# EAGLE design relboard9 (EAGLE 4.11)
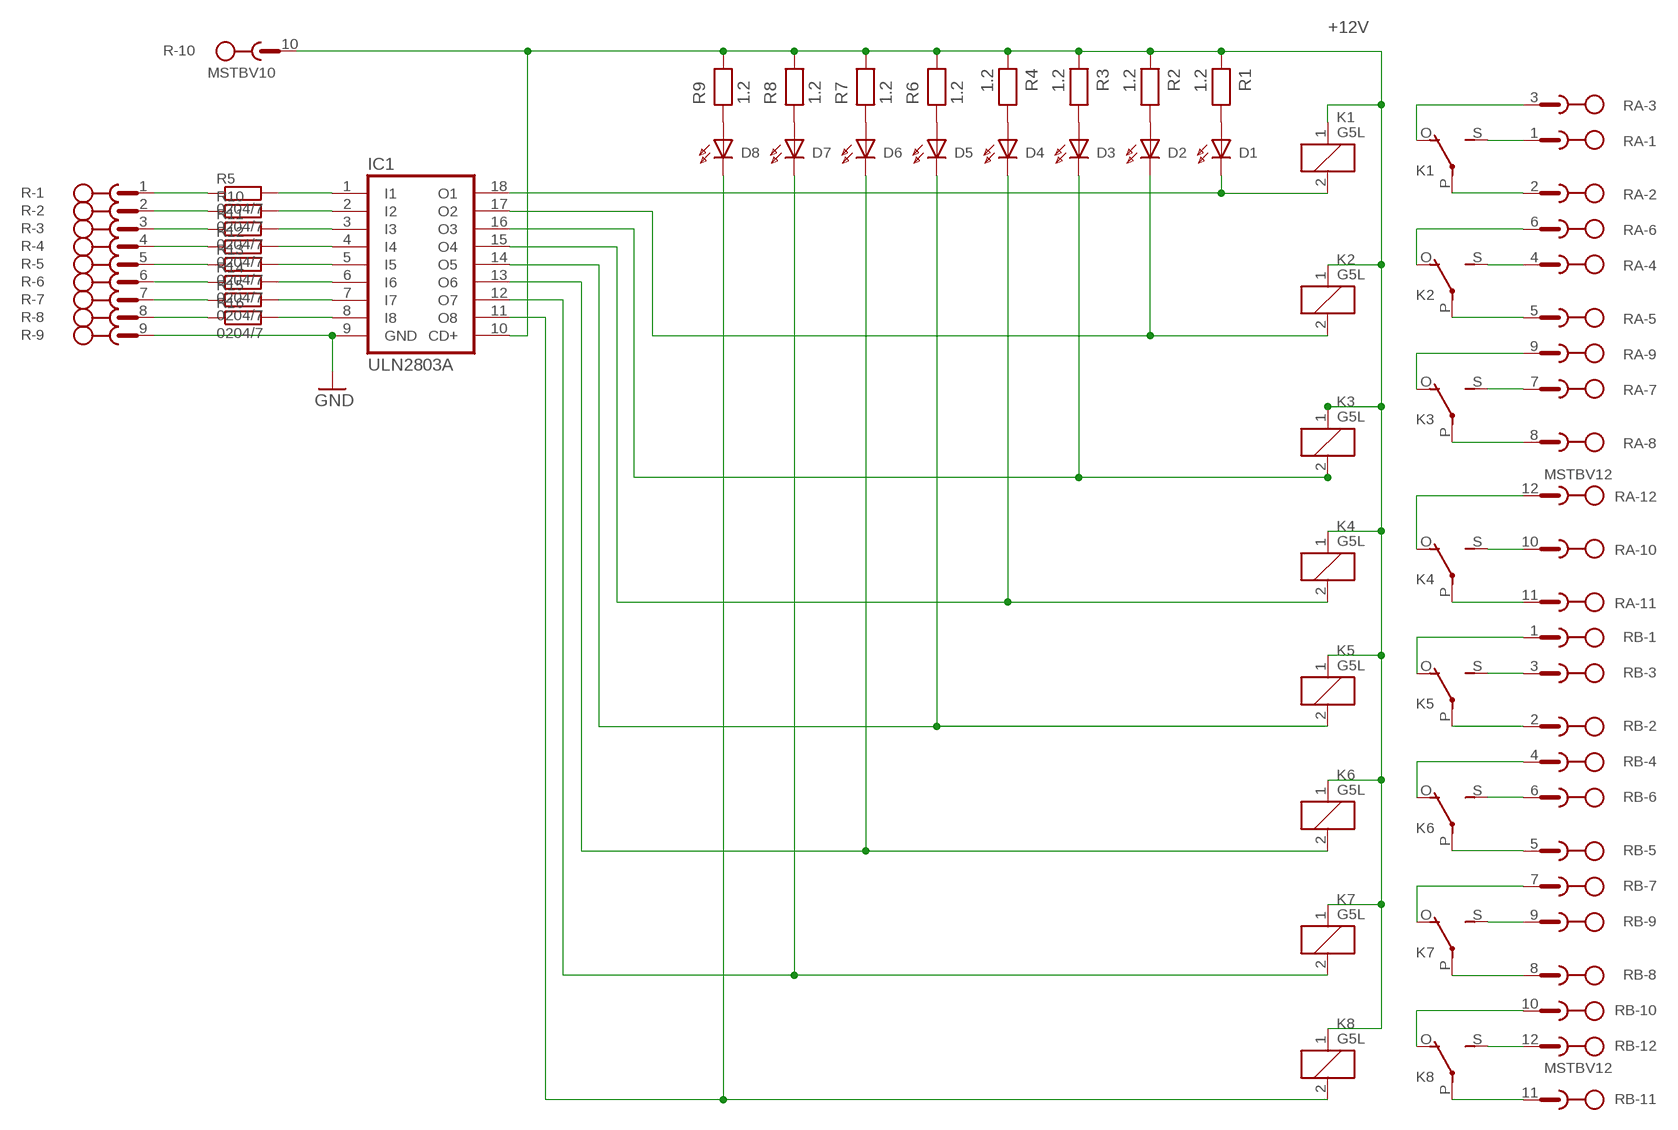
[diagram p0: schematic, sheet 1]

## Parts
D1  LED3  [LED3]
D2  LED3  [LED3]
D3  LED3  [LED3]
D4  LED3  [LED3]
D5  LED3  [LED3]
D6  LED3  [LED3]
D7  LED3  [LED3]
D8  LED3  [LED3]
IC1  ULN2803A  [DIL18]
K1  G5L  [G5L]
K2  G5L  [G5L]
K3  G5L  [G5L]
K4  G5L  [G5L]
K5  G5L  [G5L]
K6  G5L  [G5L]
K7  G5L  [G5L]
K8  G5L  [G5L]
R  MSTBV10  [MSTBV10]
R1  1.2  RESEU-10  [R-10]
R2  1.2  RESEU-10  [R-10]
R3  1.2  RESEU-10  [R-10]
R4  1.2  RESEU-10  [R-10]
R5  0204/7  [0204/7]
R6  1.2  RESEU-10  [R-10]
R7  1.2  RESEU-10  [R-10]
R8  1.2  RESEU-10  [R-10]
R9  1.2  RESEU-10  [R-10]
R10  0204/7  [0204/7]
R11  0204/7  [0204/7]
R12  0204/7  [0204/7]
R13  0204/7  [0204/7]
R14  0204/7  [0204/7]
R15  0204/7  [0204/7]
R16  0204/7  [0204/7]
RA  MSTBV12  [MSTBV12]
RB  MSTBV12  [MSTBV12]

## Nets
+12V: IC1.10(CD+) K1.1 K2.1 K3.1 K4.1 K5.1 K6.1 K7.1 K8.1 R1.1 R2.1 R3.1 R4.1 R6.2 R7.2 R8.2 R9.2 R.10
GND: IC1.9(GND) R.9
N$1: D3.K IC1.16(O3) K3.2
N$2: D2.K IC1.17(O2) K2.2
N$3: K4.P(S:P) RA.11
N$4: K2.S(S:S) RA.4
N$5: K4.S(S:S) RA.10
N$6: K2.P(S:P) RA.5
N$7: IC1.5(I5) R13.2
N$8: K3.O(S:O) RA.9
N$9: K1.P(S:P) RA.2
N$10: K1.S(S:S) RA.1
N$11: K3.P(S:P) RA.8
N$12: K4.O(S:O) RA.12
N$13: K3.S(S:S) RA.7
N$14: IC1.6(I6) R14.2
N$15: K2.O(S:O) RA.6
N$16: K1.O(S:O) RA.3
N$17: K5.S(S:S) RB.3
N$18: IC1.7(I7) R15.2
N$19: D4.K IC1.15(O4) K4.2
N$20: IC1.8(I8) R16.2
N$21: IC1.2(I2) R10.2
N$22: IC1.3(I3) R11.2
N$23: IC1.4(I4) R12.2
N$24: IC1.1(I1) R5.2
N$25: D1.A R1.2
N$26: D2.A R2.2
N$27: D3.A R3.2
N$28: D4.A R4.2
N$29: D8.K IC1.11(O8) K8.2
N$30: D7.K IC1.12(O7) K7.2
N$31: D6.K IC1.13(O6) K6.2
N$32: D5.K IC1.14(O5) K5.2
N$33: D1.K IC1.18(O1) K1.2
N$35: D5.A R6.1
N$36: D6.A R7.1
N$37: R5.1 R.1
N$38: R10.1 R.2
N$39: D7.A R8.1
N$40: D8.A R9.1
N$41: K5.O(S:O) RB.1
N$42: K5.P(S:P) RB.2
N$43: R11.1 R.3
N$44: K7.O(S:O) RB.7
N$45: K6.S(S:S) RB.6
N$46: K8.S(S:S) RB.12
N$47: K6.P(S:P) RB.5
N$48: K6.O(S:O) RB.4
N$49: K8.P(S:P) RB.11
N$50: K7.P(S:P) RB.8
N$51: K8.O(S:O) RB.10
N$52: R12.1 R.4
N$53: R13.1 R.5
N$54: R14.1 R.6
N$55: K7.S(S:S) RB.9
N$56: R15.1 R.7
N$57: R16.1 R.8

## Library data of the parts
D1-D8 = led:LED3
IC1 = uln:ULN2803A
K1-K8 = relais:G5L
R = pho508e:MSTBV10
R1-R4 R6-R9 = discrete:RESEU-10
R5 R10-R16 = r:0204/7
RA RB = pho508e:MSTBV12

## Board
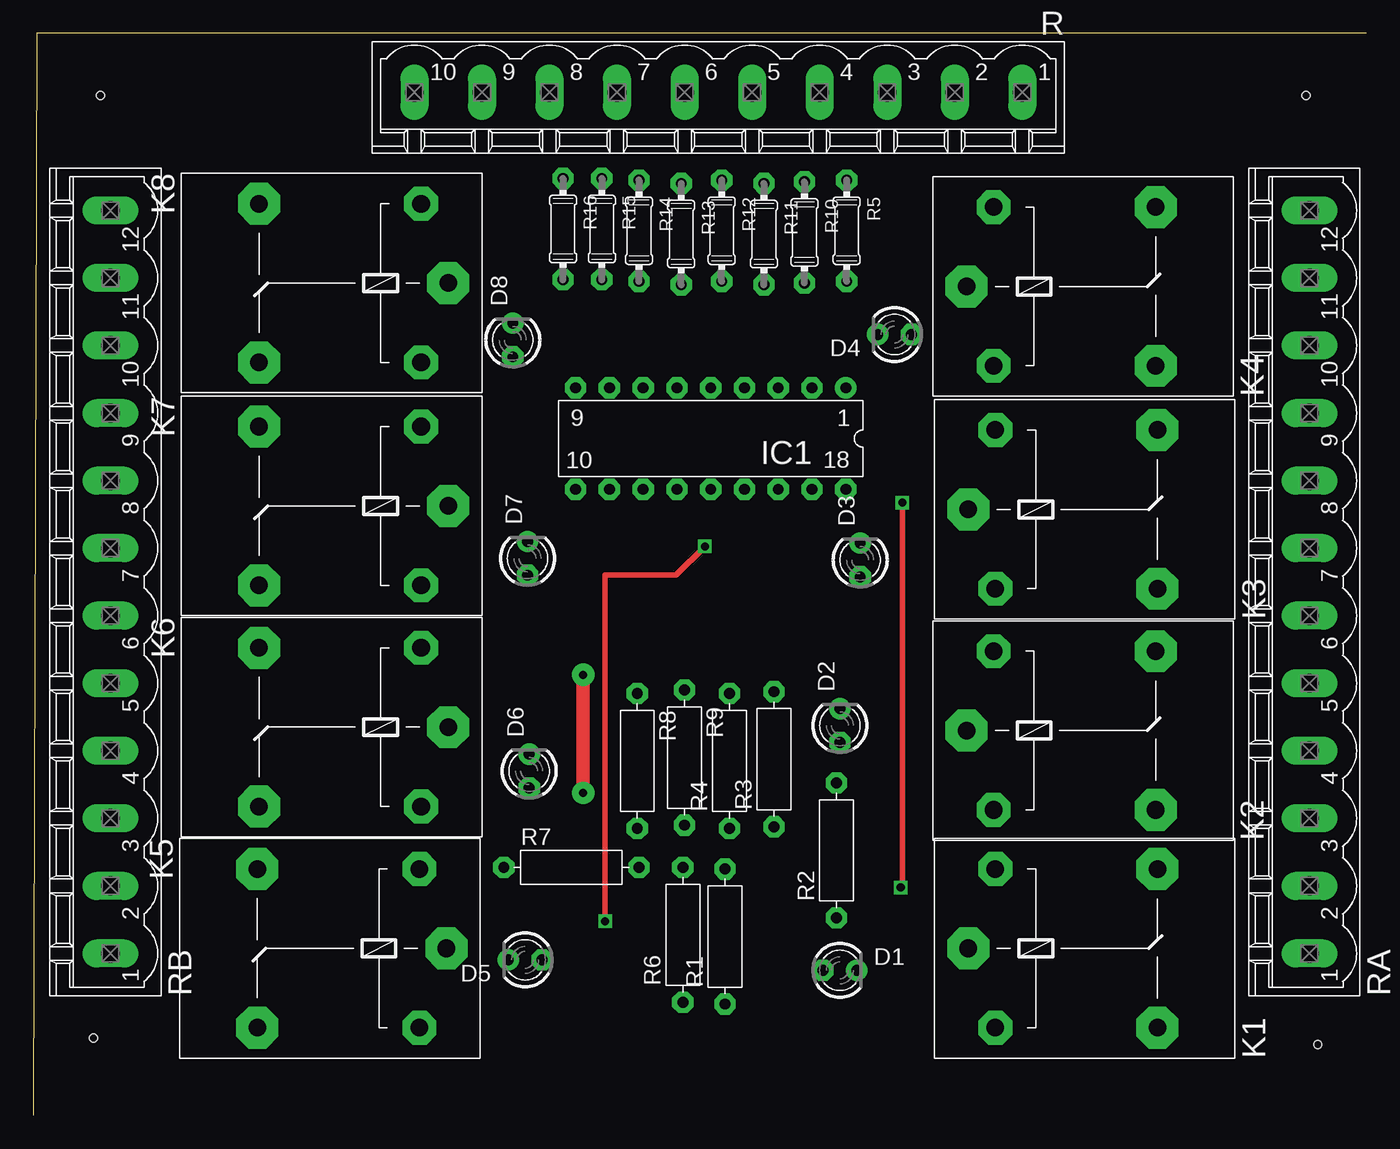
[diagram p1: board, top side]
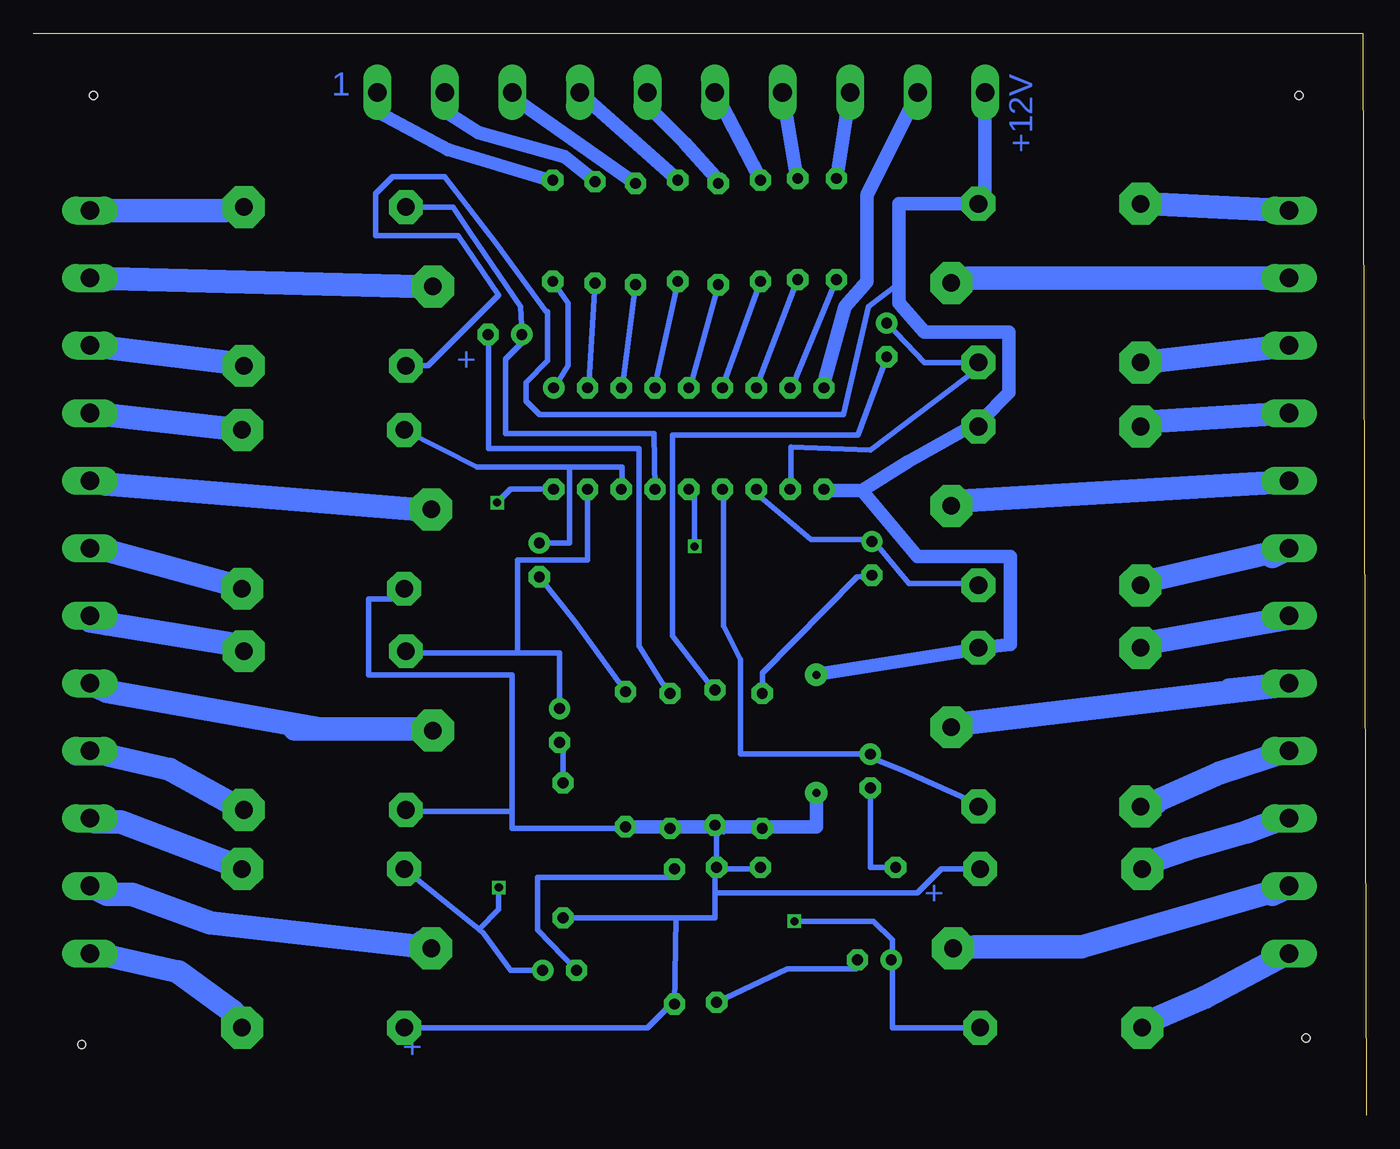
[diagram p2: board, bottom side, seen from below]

Size 100.25 x 81.4 mm. Coordinates in mm from the lower left corner, seen from the top.
Outline: 100.25,81.4 0.25,81.4 0,0
Copper layers (1*16): Top 0.035mm / dielectric 1.5mm / Bottom 0.035mm
Design rules "default": minimum track width 10mil, minimum drill 24mil, track to track 8mil, track to pad 8mil, pad to pad 8mil, via to via 8mil, smd to smd 8mil, copper to edge 40mil, drill to drill 8mil, minimum pad ring 10mil, minimum via ring 8mil, stop-mask expansion 0mil, vias tented up to drill 0mil, thermal gap 10mil
Holes 0.61 mm at 5.04,76.7 95.72,76.7 96.61,5.33 4.53,5.84

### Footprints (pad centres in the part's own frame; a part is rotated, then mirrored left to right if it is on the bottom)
LED3 = drill 0.813 pad 1.6 octagon: A -1.27,0 | drill 0.813 pad 1.6 round: K 1.27,0
DIL18 = drill 0.813 pad 1.6 round: 1 -10.16,-3.81 | drill 0.813 pad 1.6 octagon: 2 -7.62,-3.81; 3 -5.08,-3.81; 4 -2.54,-3.81; 5 0,-3.81; 6 2.54,-3.81; 7 5.08,-3.81; 8 7.62,-3.81; 9 10.16,-3.81; 10 10.16,3.81; 11 7.62,3.81; 12 5.08,3.81; 13 2.54,3.81; 14 0,3.81; 15 -2.54,3.81; 16 -5.08,3.81; 17 -7.62,3.81; 18 -10.16,3.81
G5L = drill 1.321 pad 2.54 octagon: 1 2.032,-5.969; 2 2.032,5.969 | drill 1.321 pad 3.15 octagon: O 14.224,5.969; P 0,0; S 14.224,-5.969
MSTBV10 = drill 1.397 pad 1.905 long: 1 -22.86,0; 2 -17.78,0; 3 -12.7,0; 4 -7.62,0; 5 -2.54,0; 6 2.54,0; 7 7.62,0; 8 12.7,0; 9 17.78,0; 10 22.86,0
R-10 = drill 0.813 pad 1.6 octagon: 1 -5.08,0; 2 5.08,0
0204/7 = drill 0.813 pad 1.6 octagon: 1 -3.81,0; 2 3.81,0
MSTBV12 = drill 1.397 pad 1.905 long: 1 -27.94,0; 2 -22.86,0; 3 -17.78,0; 4 -12.7,0; 5 -7.62,0; 6 -2.54,0; 7 2.54,0; 8 7.62,0; 9 12.7,0; 10 17.78,0; 11 22.86,0; 12 27.94,0

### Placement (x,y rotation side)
D1  60.67,10.92 0 top
D2  60.67,29.33 90 top
D3  62.19,41.78 90 top
D4  64.77,58.74 180 top
D5  36.99,11.7 180 top
D6  37.3,25.9 90 top
D7  37.17,41.91 90 top
D8  36.07,58.33 90 top
IC1  50.95,50.91 180 top
K1  70.32,12.57 0 top
K2  70.19,28.95 0 top
K3  70.32,45.59 0 top
K4  70.19,62.35 0 top
K5  31.08,12.57 180 top
K6  31.2,29.21 180 top
K7  31.2,45.84 180 top
K8  31.2,62.61 180 top
R  51.52,76.96 180 top
R1  52.03,13.46 90 top
R2  60.41,19.93 90 top
R3  55.71,26.79 90 top
R4  52.37,26.67 90 top
R5  61.18,66.54 270 top
R6  48.86,13.58 90 top
R7  40.47,18.66 0 top
R8  45.43,26.67 270 top
R9  48.98,26.92 270 top
R10  58,66.42 270 top
R11  54.95,66.29 270 top
R12  51.78,66.54 270 top
R13  48.73,66.29 270 top
R14  45.55,66.54 270 top
R15  42.76,66.67 270 top
R16  39.84,66.67 270 top
RA  95.97,40.13 90 top
RB  5.8,40.13 90 top

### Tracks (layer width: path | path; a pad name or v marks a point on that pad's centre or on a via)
+12V  (via drill 0.61 pad 1.68)
  Top 1.016: v41.36,24.25 v41.36,33.14
  Bottom 0.406: 45.81,21.71 R8.2 45.17,21.71 | R9.2 48.35,21.71 48.48,21.59 48.86,21.97 48.98,21.97 48.35,21.33 48.86,21.59 | 52.16,21.71 R4.1 52.79,21.71 | 28.66,69.34 K8.1 29.3,68.07 | 29.3,51.81 K7.1 | 40.73,46.98 IC1.10 | K7.1 29.43,51.94 | 28.6,76.39 28.54,76.32 | 28.6,76.39 28.66,76.45 R.10 28.66,76.32 28.6,76.39 | 28.92,51.94 28.92,52.32 | K7.1 28.66,51.56 | K6.1 31.33,34.67 28.99,35.13 | R6.2 48.86,21.59 | K1.1 54.06,6.6 52.29,8.38 R1.1 51.9,14.85 | R7.2 45.81,18.54 48.35,18.54 R6.2 | 51.9,14.85 48.98,14.85 48.98,16.76 | 48.98,16.76 48.98,17.9 R6.2 | 48.98,16.76 33.74,16.76 31.97,18.54 K5.1 | 64.22,22.86 71.84,22.86 K2.1 | 64.22,22.86 64.22,21.59 48.86,21.59 | 64.22,22.86 64.22,33.14 75.02,33.14 75.02,38.86 73.11,38.86 K3.1 | 51.9,14.85 R2.1 | K4.1 70.57,56.38 65.24,61.72 68.29,66.16 74.51,66.16 74.51,69.34 73.24,70.61 69.3,70.61 65.49,65.65 61.56,60.32 | 61.56,60.32 61.56,56.76 63.21,55.11 63.21,53.72 62.19,52.7 39.33,52.7 37.43,60.83 35.27,62.48 35.14,68.45 29.3,68.58 29.17,68.45 | 61.56,60.32 61.56,60.45 | 35.14,61.21 35.01,61.08 35.08,61.02
  Bottom 1.016: 48.35,21.71 45.81,21.71 | 52.16,21.71 49.62,21.71 R9.2 | 52.79,21.71 R3.1 | 28.66,69.34 28.66,76.32 | 37.93,46.98 34.51,49.14 29.55,51.94 29.3,51.81 | 37.93,46.98 33.74,42.03 26.76,42.03 26.76,35.43 K6.1 | 37.93,46.98 40.73,46.98 | 35.14,61.08 35.08,61.02 33.24,58.92 26.89,58.92 26.89,54.35 28.92,52.32 | K8.1 29.3,68.58 35.14,68.58 35.14,68.45 35.14,61.21 | 28.66,51.56 28.92,51.94 | 45.17,21.71 41.36,21.71 v41.36,24.25 | v41.36,33.14 41.62,33.14 28.99,35.13 28.92,35.17
GND
  Bottom 0.406: IC1.9 40.73,55.37 | 33.74,76.83 R.9
  Bottom 1.016: 40.73,55.37 39.2,60.83 37.55,62.73 37.55,69.21 33.74,76.83
N$1
  Bottom 0.406: 59.91,48.76 66.89,48.76 K3.2 | 59.91,48.76 55.97,48.76 55.97,47.11 IC1.16 | 59.91,48.76 59.91,43.05 | 59.91,43.05 59.91,43.3 | 59.91,43.05 D3.K
N$2
  Bottom 0.406: 63.84,34.79 70.95,34.79 K2.2 71.97,34.79 63.84,34.79 | IC1.17 58.57,41.78 63.84,41.78 63.84,34.79 | 63.84,34.79 60.67,34.79 D2.K
N$3
  Bottom 0.406: K4.P 71.21,62.35
  Bottom 1.778: 71.21,62.35 RA.11
N$4
  Bottom 1.778: K2.S 85.43,23.49 90.01,26.03 95.09,27.17 96.99,27.17 RA.4
N$5
  Bottom 1.778: K4.S 84.54,56.51 RA.10
N$6
  Bottom 1.778: 78.7,29.08 69.69,29.08 K2.P | 78.7,29.08 80.61,29.08 | 78.7,29.08 94.7,31.87 RA.5
N$7
  Bottom 0.406: IC1.5 50.89,54.61 R13.2
N$8
  Bottom 1.778: K3.O RA.9
N$9
  Bottom 1.778: K1.P 70.7,13.08 70.95,13.08 70.95,12.7 86.96,14.47 92.8,16.63 94.7,16.63 RA.2
N$10
  Bottom 1.778: K1.S 85.18,7.74 89.37,10.79 94.83,12.06 RA.1
N$11
  Bottom 1.778: K3.P 69.94,45.46 94.83,47.49 RA.8
N$12
  Bottom 1.778: K4.O 85.81,68.07 RA.12
N$13
  Bottom 1.778: K3.S 85.05,39.87 94.83,42.54 94.7,42.67 RA.7
N$14
  Bottom 0.406: IC1.6 48.48,54.61 R14.2
N$15
  Bottom 0.406: 95.97,37.21 94.7,36.95
  Bottom 1.778: 95.97,37.21 84.42,35.3 K2.O | 94.7,36.95 RA.6
N$16
  Bottom 1.778: K1.O 85.05,18.66 85.05,18.79 93.69,22.09 95.59,22.09 RA.3
N$17
  Bottom 1.778: K5.S 15.58,19.3 13.42,20.06 8.98,21.33 6.57,22.22 RB.3
N$18
  Bottom 0.406: IC1.7 45.94,54.61 R15.2
N$19
  Bottom 0.406: K4.2 68.67,68.32 67.4,66.42 63.59,60.83 D4.K 63.5,58.67 | IC1.15 53.56,51.3 64.73,51.3 64.73,56.89 63.59,58.03 63.59,58.67 63.5,58.67 | 63.5,58.67 63.46,58.67
N$20
  Bottom 0.406: IC1.8 43.27,54.61 R16.2
N$21
  Bottom 0.406: IC1.2 58.51,54.61 R10.2
N$22
  Bottom 0.406: IC1.3 55.97,54.61 R11.2
N$23
  Bottom 0.406: IC1.4 53.56,54.61 R12.2
N$24
  Bottom 0.406: R5.2 60.03,61.08 60.03,56.38 61.05,54.73 IC1.1
N$25
  Bottom 0.406: R1.2 52.16,17.9 62.32,17.9 62.32,13.96 D1.A
N$26
  Bottom 0.406: R2.2 60.41,27.43 D2.A
N$27
  Bottom 0.406: R3.2 59.52,37.21 D3.A
N$28
  Bottom 0.406: R4.2 52.41,32 52.54,31.87 54.7,35.3 54.7,50.16 66,50.16 66,58.54 66.13,58.54 D4.A
N$29
  Bottom 0.406: D8.K 33.24,56.64 30.44,56.64 29.05,56.51 K8.2 29.81,55.88 28.92,56.38 37.3,50.03 43.27,50.29 43.27,47.75 | 43.27,47.75 43.27,47.62 | 43.27,47.75 IC1.11
N$30
  Bottom 0.406: K7.2 29.93,40 34.38,40 36.92,43.05 D7.K 37.55,43.3 41.74,43.3 45.81,46.73 45.81,46.48 IC1.12
N$31
  Bottom 0.406: K6.2 29.05,23.36 34.76,25.9 36.92,26.79 D6.K 47.08,27.17 47.08,34.29 48.35,36.83 48.35,46.86 IC1.13
N$32  (via drill 0.61)
  Top 0.406: v43.01,14.6 43.01,40.63 48.35,40.63 v50.51,42.79
  Bottom 0.406: K5.2 35.65,6.6 35.65,11.7 D5.K 35.9,11.93 35.65,11.81 35.65,13.2 37.05,14.6 v43.01,14.6 | 51.01,47.1 51.02,47.11 | 51.01,47.1 IC1.14 | v50.51,42.79 50.51,46.6 51.01,47.1
N$33  (via drill 0.61)
  Top 0.406: v65.37,46.1 65.37,17.27 v65.24,17.14
  Bottom 0.406: IC1.18 61.18,47.11 64.35,47.11 v65.37,46.1 | 66.72,13.99 66.38,13.71 64.35,10.92 D1.K 61.81,10.92 | 66.72,13.99 K1.2 | 66.72,13.99 66.72,14.01 65.24,15.49 v65.24,17.14
N$35
  Bottom 0.406: D5.A 38.39,11.04 43.52,11.04 R6.1
N$36
  Bottom 0.406: 35.27,18.66 R7.1 37.3,18.66 D6.A
N$37
  Bottom 0.406: 61.43,70.35 61.68,70.61 R5.1 | 74.26,75.43 R.1
  Bottom 1.016: 61.43,70.35 69.05,72.64 74.26,75.43
N$38
  Bottom 0.406: 58.25,70.48 59.14,70.99 58.51,70.61 R10.1 | 68.92,75.31 R.2
  Bottom 1.016: 58.25,70.48 60.29,72.13 66.76,73.91 68.92,75.31
N$39
  Bottom 0.406: 45.43,31.62 R8.1 45.43,33.27 38.32,40.51 37.3,40.63 D7.A
N$40
  Bottom 0.406: D8.A 38.22,51.18 52.16,51.18 52.16,36.06 48.98,31.87 R9.1
N$41
  Bottom 1.778: K5.O 15.96,7.23 12.15,8.88 6.19,12.06 RB.1
N$42
  Bottom 1.778: K5.P 29.43,12.7 21.43,12.7 5.93,17.14 7.07,16.63 RB.2
N$43
  Bottom 0.406: 63.46,76.07 63.33,75.81 63.59,75.69 R.3
  Bottom 1.016: R11.1 63.46,76.07
N$44
  Bottom 0.406: 7.07,42.03 5.17,42.79 | 16.73,40.13 K7.O
  Bottom 1.778: 5.17,42.79 16.73,40.13 | 7.07,42.03 RB.7
N$45
  Bottom 0.406: 5.55,37.46 7.07,36.95 RB.6 | 17.11,35.43 K6.S
  Bottom 1.778: 5.55,37.46 17.11,35.43
N$46
  Bottom 0.406: 16.47,68.58 K8.S
  Bottom 1.778: RB.12 16.47,68.58
N$47
  Bottom 0.406: 5.93,32.38 RB.5
  Bottom 1.778: 5.93,32.38 31.46,29.33 K6.P | RB.5 10.25,32
N$48
  Bottom 0.406: 16.09,23.49 15.84,23.49
  Bottom 1.778: 16.09,23.49 11.01,25.78 5.93,27.43 RB.4 | 15.84,23.49 K6.O
N$49
  Bottom 1.778: K8.P 29.93,62.99 RB.11
N$50
  Bottom 1.778: K7.P 30.57,46.22 6.95,47.62 RB.8
N$51
  Bottom 1.778: K8.O 16.85,56.64 RB.10
N$52
  Bottom 0.406: 58.89,76.7 R.4
  Bottom 1.016: R12.1 58.89,76.7
N$53
  Bottom 0.406: 48.98,70.61 48.35,70.61 R13.1 | 53.68,75.56 R.5
  Bottom 1.016: 48.98,70.61 51.27,73.15 53.68,75.56
N$54
  Bottom 0.406: 45.68,70.61 45.43,70.1 45.81,70.61 R14.1
  Bottom 1.016: 45.68,70.61 R.6
N$55
  Bottom 1.778: K7.S 16.09,52.19 RB.9
N$56
  Bottom 0.406: R15.1 42.76,70.23
  Bottom 1.016: 42.76,70.23 R.7
N$57
  Bottom 0.406: 39.84,70.35 39.97,70.73 R16.1
  Bottom 1.016: 39.84,70.35 R.8

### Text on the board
Bottom: +12V | 1 | + | + | + | +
